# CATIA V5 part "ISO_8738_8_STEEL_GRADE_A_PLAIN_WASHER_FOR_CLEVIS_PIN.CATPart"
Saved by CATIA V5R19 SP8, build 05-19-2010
Part number: ISO 8738 WASHER 8 STEEL GRADE A PLAIN WASHER FOR CLEVIS PIN
Nomenclature: 33
Publications: "Mating Face", "Axis"
Bounding box of the stored display mesh (mm): x 0 to 2.2, y -7.5 to 7.5, z -7.49 to 7.49
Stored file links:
  C:\Users\rphgr\Desktop\0_Tapis_TC520B_vitesse\ISO_8738_8_STEEL_GRADE_A_PLAIN_WASHER_FOR_CLEVIS_PIN.CATPart
  C:\Program Files\Dassault Systemes\B19\win_b64\startup\components\MechanicalStandardParts\ISO_Standards\Design_Tables\ISO_8738_PLAIN_WASHERS_FOR_CLEVIS_PINS.txt
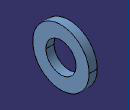
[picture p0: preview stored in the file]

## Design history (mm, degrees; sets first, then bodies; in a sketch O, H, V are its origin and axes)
Parameters
  Designation = "M8"
  d1_min_hole_dia = 8 mm
  d2_max_outside_hole_dia = 15 mm
  h_max_thickness = 2.2 mm
Body1 (main body)
  Sketch1 on yz-plane, origin (0, 0, 0), H (0, 1, 0), V (0, 0, 1)
    circle A1 centre (0, 0) radius 7.5
    circle A2 centre (0, 0) radius 4
    radius A1 = 7.5 {= d2_max_outside_hole_dia /2}
    radius A2 = 4 {= d1_min_hole_dia /2}
  Pad1: profile Sketch1, direction (1, 0, 0), length 2.2 {= h_max_thickness}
